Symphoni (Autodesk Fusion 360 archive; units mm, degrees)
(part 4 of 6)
sketch "Sketch2" plane through (0, 0, -5) normal (0, 0, -1) x axis (1, 0, 0)
  circle C1 centre (0, 0) radius 39
  circle C2 centre (0, 0) radius 53.6774
  circle C3 centre (0, 0) radius 55.2268
  circle C4 centre (0, 0) radius 50
  circle C5 centre (0.6259, 42.9954) radius 7
  point P1 (0, 0)
  point P3 (0, 0)
  point P4 (0, 0)
  coincident P1 P3
  coincident P1 P4
  tangent C4 C5
  dimension "d85" diameter C4 = 100
  dimension "d86" diameter C5 = 14
work_plane "WorkPlane3" AlongDistance -70
sketch "Sketch7" plane through (-70, 0, 0) normal (1, 0, 0) x axis (0, 1, 0)
  circle C1 centre (0, 0) radius 2.5
  point P1 (0, 0)
  point P2 (0, 0)
  coincident P1 P2
  dimension "d88" diameter C1 = 5
extrude "Extrude5" cut sketch "Sketch7" along normal blind 140
split "Split2"
move "Move1"
sketch "Sketch8" plane through (0, 0, 18) normal (0, 0, 1) x axis (-1, 0, 0)
  circle C1 centre (0, 0) radius 53.6774
  circle C2 centre (0, 0) radius 48.4417
  circle C3 centre (0, 0) radius 50.9417
  circle C4 centre (0, 0) radius 52.9417
  concentric C1 C3
  concentric C3 C4
  dimension "d91" distance C3 C4 = 2
  dimension "d92" distance C2 C3 = 2.5
extrude "Extrude6" add sketch "Sketch8" profile of C3 C4 along normal blind 3 taper -2
move "Move2"
combine "Combine1"
sketch "involute_gear (9)" plane through (0, 0, -5) normal (0, 0, -1) x axis (1, 0, 0)
  line L1 (54.638, 6.1152) -> (54.716, 6.3779)
  line L2 (54.5535, 5.8691) -> (54.638, 6.1152)
  line L3 (54.4648, 5.642) -> (54.5535, 5.8691)
  line L4 (54.3723, 5.4318) -> (54.4648, 5.642)
  line L5 (54.2784, 5.2404) -> (54.3723, 5.4318)
  line L6 (54.1826, 5.0642) -> (54.2784, 5.2404)
  line L7 (54.0879, 4.9062) -> (54.1826, 5.0642)
  line L8 (53.9943, 4.7639) -> (54.0879, 4.9062)
  line L9 (53.8171, 4.5275) -> (53.9943, 4.7639)
  line L10 (53.66, 4.3508) -> (53.8171, 4.5275)
  line L11 (53.5321, 4.2292) -> (53.66, 4.3508)
  line L12 (53.459, 4.1692) -> (53.5321, 4.2292)
  line L13 (53.3037, 4.1163) -> (53.459, 4.1692)
  line L14 (53.1104, 4.0419) -> (53.3037, 4.1163)
  line L15 (52.9362, 3.9591) -> (53.1104, 4.0419)
  line L16 (52.7815, 3.8694) -> (52.9362, 3.9591)
  line L17 (52.6463, 3.7745) -> (52.7815, 3.8694)
  line L18 (52.531, 3.6756) -> (52.6463, 3.7745)
  line L19 (52.4355, 3.5744) -> (52.531, 3.6756)
  line L20 (52.3599, 3.4723) -> (52.4355, 3.5744)
  line L21 (52.3039, 3.3708) -> (52.3599, 3.4723)
  line L22 (52.2674, 3.2713) -> (52.3039, 3.3708)
  line L23 (52.2502, 3.1753) -> (52.2674, 3.2713)
  line L24 (52.2517, 3.0842) -> (52.2502, 3.1753)
  line L25 (52.2754, 2.9893) -> (52.2517, 3.0842)
  line L26 (52.376, 2.7657) -> (52.2754, 2.9893)
  line L27 (52.5309, 2.377) -> (52.376, 2.7657)
  line L28 (52.6621, 1.9798) -> (52.5309, 2.377)
  line L29 (52.7287, 1.7438) -> (52.6621, 1.9798)
  line L30 (52.7716, 1.6559) -> (52.7287, 1.7438)
  line L31 (52.8289, 1.5851) -> (52.7716, 1.6559)
  line L32 (52.9039, 1.5227) -> (52.8289, 1.5851)
  line L33 (52.9957, 1.4699) -> (52.9039, 1.5227)
  line L34 (53.1039, 1.4281) -> (52.9957, 1.4699)
  line L35 (53.2275, 1.3985) -> (53.1039, 1.4281)
  line L36 (53.3657, 1.3823) -> (53.2275, 1.3985)
  line L37 (53.5176, 1.3808) -> (53.3657, 1.3823)
  line L38 (53.6821, 1.3949) -> (53.5176, 1.3808)
  line L39 (53.8583, 1.4257) -> (53.6821, 1.3949)
  line L40 (54.0449, 1.4742) -> (53.8583, 1.4257)
  line L41 (54.2409, 1.5414) -> (54.0449, 1.4742)
  line L42 (54.3938, 1.6008) -> (54.2409, 1.5414)
  line L43 (54.4884, 1.6018) -> (54.3938, 1.6008)
  line L44 (54.6645, 1.5908) -> (54.4884, 1.6018)
  line L45 (54.8985, 1.5564) -> (54.6645, 1.5908)
  line L46 (55.1861, 1.4893) -> (54.8985, 1.5564)
  line L47 (55.3493, 1.4404) -> (55.1861, 1.4893)
  line L48 (55.5234, 1.3802) -> (55.3493, 1.4404)
  line L49 (55.71, 1.3069) -> (55.5234, 1.3802)
  line L50 (55.905, 1.2206) -> (55.71, 1.3069)
  line L51 (56.111, 1.119) -> (55.905, 1.2206)
  line L52 (56.3249, 1.0021) -> (56.111, 1.119)
  line L53 (56.5479, 0.8678) -> (56.3249, 1.0021)
  line L54 (56.7765, 0.7168) -> (56.5479, 0.8678)
  line L55 (56.9853, 0.566) -> (56.7765, 0.7168)
  line L56 (56.7765, -0.7168) -> (56.9853, -0.566)
  line L57 (56.5479, -0.8678) -> (56.7765, -0.7168)
  line L58 (56.3249, -1.0021) -> (56.5479, -0.8678)
  line L59 (56.111, -1.119) -> (56.3249, -1.0021)
  line L60 (55.905, -1.2206) -> (56.111, -1.119)
  line L61 (55.71, -1.3069) -> (55.905, -1.2206)
  line L62 (55.5234, -1.3802) -> (55.71, -1.3069)
  line L63 (55.3493, -1.4404) -> (55.5234, -1.3802)
  line L64 (55.1861, -1.4893) -> (55.3493, -1.4404)
  line L65 (54.8985, -1.5564) -> (55.1861, -1.4893)
  line L66 (54.6645, -1.5908) -> (54.8985, -1.5564)
  line L67 (54.4884, -1.6018) -> (54.6645, -1.5908)
  line L68 (54.3938, -1.6008) -> (54.4884, -1.6018)
  line L69 (54.2409, -1.5414) -> (54.3938, -1.6008)
  line L70 (54.0449, -1.4742) -> (54.2409, -1.5414)
  line L71 (53.8583, -1.4257) -> (54.0449, -1.4742)
  line L72 (53.6821, -1.3949) -> (53.8583, -1.4257)
  line L73 (53.5176, -1.3808) -> (53.6821, -1.3949)
  line L74 (53.3657, -1.3823) -> (53.5176, -1.3808)
  line L75 (53.2275, -1.3985) -> (53.3657, -1.3823)
  line L76 (53.1039, -1.4281) -> (53.2275, -1.3985)
  line L77 (52.9957, -1.4699) -> (53.1039, -1.4281)
  line L78 (52.9039, -1.5227) -> (52.9957, -1.4699)
  line L79 (52.8289, -1.5851) -> (52.9039, -1.5227)
  line L80 (52.7716, -1.6559) -> (52.8289, -1.5851)
  line L81 (52.7287, -1.7438) -> (52.7716, -1.6559)
  line L82 (52.6621, -1.9798) -> (52.7287, -1.7438)
  line L83 (52.5309, -2.377) -> (52.6621, -1.9798)
  line L84 (52.376, -2.7657) -> (52.5309, -2.377)
  line L85 (52.2754, -2.9893) -> (52.376, -2.7657)
  line L86 (52.2517, -3.0842) -> (52.2754, -2.9893)
  line L87 (52.2502, -3.1753) -> (52.2517, -3.0842)
  line L88 (52.2674, -3.2713) -> (52.2502, -3.1753)
  line L89 (52.3039, -3.3708) -> (52.2674, -3.2713)
  line L90 (52.3599, -3.4723) -> (52.3039, -3.3708)
  line L91 (52.4355, -3.5744) -> (52.3599, -3.4723)
  line L92 (52.531, -3.6756) -> (52.4355, -3.5744)
  line L93 (52.6463, -3.7745) -> (52.531, -3.6756)
  line L94 (52.7815, -3.8694) -> (52.6463, -3.7745)
  line L95 (52.9362, -3.9591) -> (52.7815, -3.8694)
  line L96 (53.1104, -4.0419) -> (52.9362, -3.9591)
  line L97 (53.3037, -4.1163) -> (53.1104, -4.0419)
  line L98 (53.459, -4.1692) -> (53.3037, -4.1163)
  line L99 (53.5321, -4.2292) -> (53.459, -4.1692)
  line L100 (53.66, -4.3508) -> (53.5321, -4.2292)
  line L101 (53.8171, -4.5275) -> (53.66, -4.3508)
  line L102 (53.9943, -4.7639) -> (53.8171, -4.5275)
  line L103 (54.0879, -4.9062) -> (53.9943, -4.7639)
  line L104 (54.1826, -5.0642) -> (54.0879, -4.9062)
  line L105 (54.2784, -5.2404) -> (54.1826, -5.0642)
  line L106 (54.3723, -5.4318) -> (54.2784, -5.2404)
  line L107 (54.4648, -5.642) -> (54.3723, -5.4318)
  line L108 (54.5535, -5.8691) -> (54.4648, -5.642)
  line L109 (54.638, -6.1152) -> (54.5535, -5.8691)
  line L110 (54.716, -6.3779) -> (54.638, -6.1152)
  line L111 (54.7791, -6.6277) -> (54.716, -6.3779)
  line L112 (53.7945, -7.476) -> (54.0514, -7.4948)
  line L113 (53.5223, -7.4448) -> (53.7945, -7.476)
  line L114 (53.2652, -7.4044) -> (53.5223, -7.4448)
  line L115 (53.0262, -7.3564) -> (53.2652, -7.4044)
  line L116 (52.8031, -7.3019) -> (53.0262, -7.3564)
  line L117 (52.5983, -7.2426) -> (52.8031, -7.3019)
  line L118 (52.4082, -7.1789) -> (52.5983, -7.2426)
  line L119 (52.2361, -7.1131) -> (52.4082, -7.1789)
  line L120 (52.0797, -7.0456) -> (52.2361, -7.1131)
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sketch "External_Gear1" plane through (0, 0, -5) normal (0, 0, -1) x axis (0.9995, -0.032, 0)
  line L1 (56.5597, -8.8414) -> (56.452, -9.1587)
  line L2 (56.6721, -8.5508) -> (56.5597, -8.8414)
  line L3 (56.7891, -8.2821) -> (56.6721, -8.5508)
  line L4 (56.9077, -8.0385) -> (56.7891, -8.2821)
  line L5 (57.0253, -7.8204) -> (56.9077, -8.0385)
  line L6 (57.1424, -7.6235) -> (57.0253, -7.8204)
  line L7 (57.2543, -7.4522) -> (57.1424, -7.6235)
  line L8 (57.3622, -7.3011) -> (57.2543, -7.4522)
  line L9 (57.4622, -7.1728) -> (57.3622, -7.3011)
  line L10 (57.6361, -6.9758) -> (57.4622, -7.1728)
  line L11 (57.7628, -6.8542) -> (57.6361, -6.9758)
  line L12 (57.8308, -6.7991) -> (57.7628, -6.8542)
  line L13 (58.0327, -6.6822) -> (57.8308, -6.7991)
  line L14 (58.2072, -6.5612) -> (58.0327, -6.6822)
  line L15 (58.3543, -6.4383) -> (58.2072, -6.5612)
  line L16 (58.4741, -6.3156) -> (58.3543, -6.4383)
  line L17 (58.567, -6.195) -> (58.4741, -6.3156)
  line L18 (58.6334, -6.0786) -> (58.567, -6.195)
  line L19 (58.6739, -5.9684) -> (58.6334, -6.0786)
  line L20 (58.6891, -5.8663) -> (58.6739, -5.9684)
  line L21 (58.6798, -5.7743) -> (58.6891, -5.8663)
  line L22 (58.6524, -5.7035) -> (58.6798, -5.7743)
  line L23 (58.4547, -5.3658) -> (58.6524, -5.7035)
  line L24 (58.3043, -5.0887) -> (58.4547, -5.3658)
  line L25 (58.1617, -4.8075) -> (58.3043, -5.0887)
  line L26 (57.9961, -4.453) -> (58.1617, -4.8075)
  line L27 (57.9534, -4.3902) -> (57.9961, -4.453)
  line L28 (57.883, -4.3303) -> (57.9534, -4.3902)
  line L29 (57.7903, -4.2848) -> (57.883, -4.3303)
  line L30 (57.6766, -4.2555) -> (57.7903, -4.2848)
  line L31 (57.5431, -4.244) -> (57.6766, -4.2555)
  line L32 (57.3911, -4.252) -> (57.5431, -4.244)
  line L33 (57.222, -4.2809) -> (57.3911, -4.252)
  line L34 (57.0373, -4.3321) -> (57.222, -4.2809)
  line L35 (56.8386, -4.407) -> (57.0373, -4.3321)
  line L36 (56.6277, -4.5068) -> (56.8386, -4.407)
  line L37 (56.5437, -4.5315) -> (56.6277, -4.5068)
  line L38 (56.3716, -4.5666) -> (56.5437, -4.5315)
  line L39 (56.1108, -4.5978) -> (56.3716, -4.5666)
  line L40 (55.9484, -4.6072) -> (56.1108, -4.5978)
  line L41 (55.7627, -4.6102) -> (55.9484, -4.6072)
  line L42 (55.5582, -4.605) -> (55.7627, -4.6102)
  line L43 (55.3296, -4.5895) -> (55.5582, -4.605)
  line L44 (55.0833, -4.5624) -> (55.3296, -4.5895)
  line L45 (54.8155, -4.5216) -> (55.0833, -4.5624)
  line L46 (54.5279, -4.4653) -> (54.8155, -4.5216)
  line L47 (54.2248, -4.3927) -> (54.5279, -4.4653)
  line L48 (53.9026, -4.3011) -> (54.2248, -4.3927)
  line L49 (53.6006, -4.2018) -> (53.9026, -4.3011)
  line L50 (53.5185, -2.743) -> (53.2973, -2.9712)
  line L51 (53.7613, -2.5121) -> (53.5185, -2.743)
  line L52 (53.9959, -2.307) -> (53.7613, -2.5121)
  line L53 (54.2244, -2.1235) -> (53.9959, -2.307)
  line L54 (54.4426, -1.9629) -> (54.2244, -2.1235)
  line L55 (54.6481, -1.8244) -> (54.4426, -1.9629)
  line L56 (54.8433, -1.7045) -> (54.6481, -1.8244)
  line L57 (55.0219, -1.6048) -> (54.8433, -1.7045)
  line L58 (55.1877, -1.5212) -> (55.0219, -1.6048)
  line L59 (55.3359, -1.454) -> (55.1877, -1.5212)
  line L60 (55.5814, -1.3604) -> (55.3359, -1.454)
  line L61 (55.7501, -1.3116) -> (55.5814, -1.3604)
  line L62 (55.8359, -1.2944) -> (55.7501, -1.3116)
  line L63 (56.069, -1.2847) -> (55.8359, -1.2944)
  line L64 (56.2797, -1.2587) -> (56.069, -1.2847)
  line L65 (56.4671, -1.2183) -> (56.2797, -1.2587)
  line L66 (56.6303, -1.1653) -> (56.4671, -1.2183)
  line L67 (56.7686, -1.1017) -> (56.6303, -1.1653)
  line L68 (56.8815, -1.0294) -> (56.7686, -1.1017)
  line L69 (56.9685, -0.9507) -> (56.8815, -1.0294)
  line L70 (57.0294, -0.8674) -> (56.9685, -0.9507)
  line L71 (57.064, -0.7816) -> (57.0294, -0.8674)
  line L72 (57.0725, -0.7061) -> (57.064, -0.7816)
  line L73 (57.0545, -0.3152) -> (57.0725, -0.7061)
  line L74 (57.05, 0) -> (57.0545, -0.3152)
  line L75 (57.0545, 0.3152) -> (57.05, 0)
  line L76 (57.0725, 0.7061) -> (57.0545, 0.3152)
  line L77 (57.064, 0.7816) -> (57.0725, 0.7061)
  line L78 (57.0294, 0.8674) -> (57.064, 0.7816)
  line L79 (56.9685, 0.9507) -> (57.0294, 0.8674)
  line L80 (56.8815, 1.0295) -> (56.9685, 0.9507)
  line L81 (56.7686, 1.1017) -> (56.8815, 1.0295)
  line L82 (56.6303, 1.1653) -> (56.7686, 1.1017)
  line L83 (56.4671, 1.2183) -> (56.6303, 1.1653)
  line L84 (56.2797, 1.2588) -> (56.4671, 1.2183)
  line L85 (56.069, 1.2847) -> (56.2797, 1.2588)
  line L86 (55.8359, 1.2944) -> (56.069, 1.2847)
  line L87 (55.7501, 1.3116) -> (55.8359, 1.2944)
  line L88 (55.5814, 1.3604) -> (55.7501, 1.3116)
  line L89 (55.3359, 1.454) -> (55.5814, 1.3604)
  line L90 (55.1877, 1.5211) -> (55.3359, 1.454)
  line L91 (55.0219, 1.6048) -> (55.1877, 1.5211)
  line L92 (54.8433, 1.7045) -> (55.0219, 1.6048)
  line L93 (54.6481, 1.8244) -> (54.8433, 1.7045)
  line L94 (54.4426, 1.9629) -> (54.6481, 1.8244)
  line L95 (54.2244, 2.1235) -> (54.4426, 1.9629)
  line L96 (53.9959, 2.307) -> (54.2244, 2.1235)
  line L97 (53.7613, 2.5121) -> (53.9959, 2.307)
  line L98 (53.5185, 2.743) -> (53.7613, 2.5121)
  line L99 (53.2973, 2.9712) -> (53.5185, 2.743)
  line L100 (53.9026, 4.3011) -> (53.6006, 4.2018)
  line L101 (54.2248, 4.3927) -> (53.9026, 4.3011)
  line L102 (54.5279, 4.4653) -> (54.2248, 4.3927)
  line L103 (54.8155, 4.5216) -> (54.5279, 4.4653)
  line L104 (55.0833, 4.5624) -> (54.8155, 4.5216)
  line L105 (55.3296, 4.5895) -> (55.0833, 4.5624)
  line L106 (55.5582, 4.605) -> (55.3296, 4.5895)
  line L107 (55.7627, 4.6102) -> (55.5582, 4.605)
  line L108 (55.9484, 4.6072) -> (55.7627, 4.6102)
  line L109 (56.1108, 4.5978) -> (55.9484, 4.6072)
  line L110 (56.3716, 4.5666) -> (56.1108, 4.5978)
  line L111 (56.5437, 4.5315) -> (56.3716, 4.5666)
  line L112 (56.6277, 4.5068) -> (56.5437, 4.5315)
  line L113 (56.8386, 4.407) -> (56.6277, 4.5068)
  line L114 (57.0373, 4.3321) -> (56.8386, 4.407)
  line L115 (57.222, 4.2809) -> (57.0373, 4.3321)
  line L116 (57.3911, 4.252) -> (57.222, 4.2809)
  line L117 (57.5431, 4.244) -> (57.3911, 4.252)
  line L118 (57.6766, 4.2555) -> (57.5431, 4.244)
  line L119 (57.7903, 4.2848) -> (57.6766, 4.2555)
  line L120 (57.883, 4.3303) -> (57.7903, 4.2848)
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extrude "Extrude8" add sketch "External_Gear1" along normal blind 10
extrude "Extrude7" new body sketch "External_Gear1" along normal blind 10
position "Position9"
sketch "Sketch13" plane through (0, 0, -19.815) normal (0, 0, 1) x axis (-1, 0, 0)
  line L1 (-96.81, 0.1409) -> (-93.19, 0.1409)
  line L2 (-96.81, 6.3591) -> (-96.81, 0.1409)
  line L3 (-93.19, 6.3591) -> (-96.81, 6.3591)
  line L4 (-93.19, 0.1409) -> (-93.19, 6.3591)
  line L5 (-96.81, 6.3591) -> (-93.19, 0.1409)
  line L6 (-93.19, 6.3591) -> (-96.81, 0.1409)
  circle C1 centre (-95, 3.25) radius 3.5
  circle C2 centre (-95, 3.25) radius 2.5
  circle C3 centre (-95, 3.25) radius 2.5
  point P8 (-95, 3.25)
  point P3 (-95, 3.25)
  point P6 (-96.81, 6.3591)
  point P7 (-93.19, 6.3591)
  concentric C1 C3
  horizontal L1
  perpendicular L1 L2
  parallel L1 L3
  parallel L2 L4
  coincident L5 P8
  coincident L6 P8
  coincident P3 P8
  dimension "d109" distance P6 P7 = 3.62
extrude "Extrude8" new body sketch "Sketch13" profile of C2 C3 L2 L4 along normal blind 8.65
sketch "Sketch14" plane through (0, 0, -15) normal (0, 0, -1) x axis (1, 0, 0)
  line L1 (63.9478, -12.0081) -> (63.7009, -12.2082)
  line L2 (64.1993, -11.7867) -> (63.9478, -12.0081)
  line L3 (64.4245, -11.5713) -> (64.1993, -11.7867)
  line L4 (64.6275, -11.3599) -> (64.4245, -11.5713)
  line L5 (64.8069, -11.1569) -> (64.6275, -11.3599)
  line L6 (64.963, -10.9645) -> (64.8069, -11.1569)
  line L7 (65.0998, -10.7807) -> (64.963, -10.9645)
  line L8 (65.2149, -10.6116) -> (65.0998, -10.7807)
  line L9 (65.313, -10.4539) -> (65.2149, -10.6116)
  line L10 (65.393, -10.3122) -> (65.313, -10.4539)
  line L11 (65.508, -10.0761) -> (65.393, -10.3122)
  line L12 (65.5716, -9.9123) -> (65.508, -10.0761)
  line L13 (65.5964, -9.8284) -> (65.5716, -9.9123)
  line L14 (65.6267, -9.597) -> (65.5964, -9.8284)
  line L15 (65.6713, -9.3895) -> (65.6267, -9.597)
  line L16 (65.7282, -9.2064) -> (65.6713, -9.3895)
  line L17 (65.7955, -9.0486) -> (65.7282, -9.2064)
  line L18 (65.8711, -8.9165) -> (65.7955, -9.0486)
  line L19 (65.9531, -8.8105) -> (65.8711, -8.9165)
  line L20 (66.0393, -8.7307) -> (65.9531, -8.8105)
  line L21 (66.1276, -8.6775) -> (66.0393, -8.7307)
  line L22 (66.2162, -8.6507) -> (66.1276, -8.6775)
  line L23 (66.2921, -8.6489) -> (66.2162, -8.6507)
  line L24 (66.6798, -8.7015) -> (66.2921, -8.6489)
  line L25 (66.9934, -8.734) -> (66.6798, -8.7015)
  line L26 (67.3078, -8.7575) -> (66.9934, -8.734)
  line L27 (67.6987, -8.7742) -> (67.3078, -8.7575)
  line L28 (67.7731, -8.7894) -> (67.6987, -8.7742)
  line L29 (67.8555, -8.8314) -> (67.7731, -8.7894)
  line L30 (67.9331, -8.8995) -> (67.8555, -8.8314)
  line L31 (68.0038, -8.9932) -> (67.9331, -8.8995)
  line L32 (68.0657, -9.1121) -> (68.0038, -8.9932)
  line L33 (68.1168, -9.2555) -> (68.0657, -9.1121)
  line L34 (68.1551, -9.4227) -> (68.1168, -9.2555)
  line L35 (68.1788, -9.6129) -> (68.1551, -9.4227)
  line L36 (68.186, -9.8251) -> (68.1788, -9.6129)
  line L37 (68.1749, -10.0582) -> (68.186, -9.8251)
  line L38 (68.1844, -10.1451) -> (68.1749, -10.0582)
  line L39 (68.2181, -10.3176) -> (68.1844, -10.1451)
  line L40 (68.2896, -10.5703) -> (68.2181, -10.3176)
  line L41 (68.3433, -10.7239) -> (68.2896, -10.5703)
  line L42 (68.4119, -10.8965) -> (68.3433, -10.7239)
  line L43 (68.4953, -11.0833) -> (68.4119, -10.8965)
  line L44 (68.5975, -11.2883) -> (68.4953, -11.0833)
  line L45 (68.7171, -11.5053) -> (68.5975, -11.2883)
  line L46 (68.8577, -11.7369) -> (68.7171, -11.5053)
  line L47 (69.0202, -11.9808) -> (68.8577, -11.7369)
  line L48 (69.2037, -12.2327) -> (69.0202, -11.9808)
  line L49 (69.4121, -12.495) -> (69.2037, -12.2327)
  line L50 (69.6198, -12.7356) -> (69.4121, -12.495)
  line L51 (70.9982, -12.2507) -> (70.8725, -12.5427)
  line L52 (71.118, -11.9379) -> (70.9982, -12.2507)
  line L53 (71.2172, -11.6425) -> (71.118, -11.9379)
  line L54 (71.2988, -11.361) -> (71.2172, -11.6425)
  line L55 (71.3633, -11.0978) -> (71.2988, -11.361)
  line L56 (71.4121, -10.8549) -> (71.3633, -11.0978)
  line L57 (71.4478, -10.6286) -> (71.4121, -10.8549)
  line L58 (71.4712, -10.4254) -> (71.4478, -10.6286)
  line L59 (71.4847, -10.2401) -> (71.4712, -10.4254)
  line L60 (71.4897, -10.0775) -> (71.4847, -10.2401)
  line L61 (71.4818, -9.815) -> (71.4897, -10.0775)
  line L62 (71.4621, -9.6404) -> (71.4818, -9.815)
  line L63 (71.445, -9.5546) -> (71.4621, -9.6404)
  line L64 (71.3643, -9.3357) -> (71.445, -9.5546)
  line L65 (71.3073, -9.1311) -> (71.3643, -9.3357)
  line L66 (71.2727, -8.9426) -> (71.3073, -9.1311)
  line L67 (71.2589, -8.7716) -> (71.2727, -8.9426)
  line L68 (71.2645, -8.6195) -> (71.2589, -8.7716)
  line L69 (71.2877, -8.4875) -> (71.2645, -8.6195)
  line L70 (71.327, -8.3769) -> (71.2877, -8.4875)
  line L71 (71.3805, -8.2886) -> (71.327, -8.3769)
  line L72 (71.4464, -8.2238) -> (71.3805, -8.2886)
  line L73 (71.5128, -8.1869) -> (71.4464, -8.2238)
  line L74 (71.8806, -8.0533) -> (71.5128, -8.1869)
  line L75 (72.1734, -7.9363) -> (71.8806, -8.0533)
  line L76 (72.4627, -7.811) -> (72.1734, -7.9363)
  line L77 (72.8166, -7.6441) -> (72.4627, -7.811)
  line L78 (72.8896, -7.623) -> (72.8166, -7.6441)
  line L79 (72.982, -7.622) -> (72.8896, -7.623)
  line L80 (73.0823, -7.6462) -> (72.982, -7.622)
  line L81 (73.1885, -7.6963) -> (73.0823, -7.6462)
  line L82 (73.2986, -7.7727) -> (73.1885, -7.6963)
  line L83 (73.4105, -7.876) -> (73.2986, -7.7727)
  line L84 (73.5221, -8.0063) -> (73.4105, -7.876)
  line L85 (73.6315, -8.1637) -> (73.5221, -8.0063)
  line L86 (73.7364, -8.3482) -> (73.6315, -8.1637)
  line L87 (73.8349, -8.5597) -> (73.7364, -8.3482)
  line L88 (73.8838, -8.6323) -> (73.8349, -8.5597)
  line L89 (73.9937, -8.7694) -> (73.8838, -8.6323)
  line L90 (74.1745, -8.96) -> (73.9937, -8.7694)
  line L91 (74.2934, -9.071) -> (74.1745, -8.96)
  line L92 (74.4343, -9.1919) -> (74.2934, -9.071)
  line L93 (74.595, -9.3185) -> (74.4343, -9.1919)
  line L94 (74.7808, -9.4527) -> (74.595, -9.3185)
  line L95 (74.9875, -9.5892) -> (74.7808, -9.4527)
  line L96 (75.2196, -9.7289) -> (74.9875, -9.5892)
  line L97 (75.4769, -9.8693) -> (75.2196, -9.7289)
  line L98 (75.7564, -10.0071) -> (75.4769, -9.8693)
  line L99 (76.0629, -10.1425) -> (75.7564, -10.0071)
  line L100 (76.3586, -10.259) -> (76.0629, -10.1425)
  line L101 (77.3537, -9.1891) -> (77.3781, -9.5061)
  line L102 (77.3145, -8.8564) -> (77.3537, -9.1891)
  line L103 (77.265, -8.5487) -> (77.3145, -8.8564)
  line L104 (77.2065, -8.2616) -> (77.265, -8.5487)
  line L105 (77.1412, -7.9986) -> (77.2065, -8.2616)
  line L106 (77.0716, -7.7608) -> (77.1412, -7.9986)
  line L107 (76.998, -7.5439) -> (77.0716, -7.7608)
  line L108 (76.9243, -7.3531) -> (76.998, -7.5439)
  line L109 (76.8502, -7.1828) -> (76.9243, -7.3531)
  line L110 (76.7791, -7.0364) -> (76.8502, -7.1828)
  line L111 (76.65, -6.8076) -> (76.7791, -7.0364)
  line L112 (76.5514, -6.6622) -> (76.65, -6.8076)
  line L113 (76.4964, -6.5942) -> (76.5514, -6.6622)
  line L114 (76.3232, -6.4378) -> (76.4964, -6.5942)
  line L115 (76.1777, -6.2832) -> (76.3232, -6.4378)
  line L116 (76.0594, -6.1324) -> (76.1777, -6.2832)
  line L117 (75.9678, -5.9874) -> (76.0594, -6.1324)
  line L118 (75.902, -5.8501) -> (75.9678, -5.9874)
  line L119 (75.8613, -5.7224) -> (75.902, -5.8501)
  line L120 (75.8446, -5.6062) -> (75.8613, -5.7224)
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  point P679 (67.9652, 2.1729)
  point P684 (67.9652, 2.1729)
  point P682 (66.0452, -0.8271)
  point P683 (69.8852, -0.8271)
  point P681 (66.0452, 5.1729)
  coincident P679 P684
  dimension "d112" diameter = 5.57
  dimension "d113" distance P682 P683 = 3.84
  dimension "d114" distance P681 P682 = 6
  dimension "d145" = 0.2197
extrude "Extrude9" cut sketch "Sketch14" against normal blind 10
component_from_bodies "Body->Comp2"
component_from_bodies "Body->Comp3"
component_from_bodies "Body->Comp4"
as_built_joint "As-built3"
joint "Assemble3" alignAngle 0 alignOffsetX 0 alignOffsetY 0 alignOffsetZ -3
sketch "Sketch15" plane through (0, 0, -36.2) normal (0, 0, -1) x axis (1, 0, 0)
  line L1 (79.2152, 11.1729) -> (79.2152, -23.3271)
  line L2 (58.7152, 13.1729) -> (77.2152, 13.1729)
  line L3 (56.7152, -23.3271) -> (56.7152, 11.1729)
  line L4 (60.9652, -23.3271) -> (56.7152, -23.3271)
  line L5 (60.9652, -34.3271) -> (60.9652, -23.3271)
  line L6 (74.9652, -34.3271) -> (60.9652, -34.3271)
  line L7 (74.9652, -23.3271) -> (74.9652, -34.3271)
  line L8 (79.2152, -23.3271) -> (74.9652, -23.3271)
  line L9 (65.4652, -30.7993) -> (65.4652, -31.7993)
  line L10 (64.9246, -30.7993) -> (65.4652, -30.7993)
  line L11 (64.9246, -27.7993) -> (64.9246, -30.7993)
  line L12 (70.9246, -27.7993) -> (64.9246, -27.7993)
  line L13 (70.9246, -30.7993) -> (70.9246, -27.7993)
  line L14 (70.4652, -30.7993) -> (70.9246, -30.7993)
  line L15 (70.4652, -31.7993) -> (70.4652, -30.7993)
  line L16 (65.4652, -31.7993) -> (70.4652, -31.7993)
  line L17 (88.7324, 34) -> (50, 34)
  line L18 (88.7324, -38.6719) -> (88.7324, 34)
  line L19 (50, -38.6719) -> (88.7324, -38.6719)
  line L20 (50, 34) -> (50, -38.6719)
  arc A1 centre (77.2152, 11.1729) radius 2 clockwise from (77.2152, 13.1729) to (79.2152, 11.1729)
  arc A2 centre (58.7152, 11.1729) radius 2 clockwise from (56.7152, 11.1729) to (58.7152, 13.1729)
  circle C1 centre (77.2152, -21.3271) radius 1.25
  circle C2 centre (59.2152, -18.3271) radius 1.5
  circle C3 centre (58.7152, -21.3271) radius 1.25
  circle C4 centre (67.9652, 2.1729) radius 2.5
  circle C5 centre (76.7152, -18.3271) radius 1.5
  horizontal L17
  vertical L18
  horizontal L19
  vertical L20
extrude "Extrude10" new body sketch "Sketch15" along normal blind 28.8
as_built_joint "As-built4"
motion_link "MotionLink1" Value1 360 Value2 27.692 (= "( 360 / 13 ) * 1 deg")
extrude "Extrude9" add sketch "Sketch5" profile of C2 C3 L1 L2 L3 L4 L9 L10 L11 L12 against normal blind 5
fillet "Fillet1" radius 12.5 7.5
fillet "Fillet2" radius 5 5
sketch "Sketch16" plane through (0, 0, -65) normal (0, 0, -1) x axis (1, 0, 0)
  line L1 (10.1399, 28.3333) -> (9.8601, 28.3333)
  line L2 (10.1399, 58.3333) -> (10.1399, 28.3333)
  line L3 (-9.8601, 58.3333) -> (10.1399, 58.3333)
  line L4 (-9.8601, 31.6667) -> (-9.8601, 58.3333)
  line L5 (-28.3333, 10.1399) -> (-28.3333, 9.8601)
  line L6 (-58.3333, 10.1399) -> (-28.3333, 10.1399)
  line L7 (-58.3333, -9.8601) -> (-58.3333, 10.1399)
  line L8 (-31.6667, -9.8601) -> (-58.3333, -9.8601)
  arc A1 centre (0, 0) radius 30 clockwise from (9.8601, 28.3333) to (28.3333, 9.8601)
  arc A2 centre (30, 0) radius 10 clockwise from (28.3333, 9.8601) to (28.3333, -9.8601)
  arc A3 centre (0, 30) radius 10 clockwise from (-9.8601, 28.3333) to (-9.8601, 31.6667)
  arc A4 centre (-30, 0) radius 10 clockwise from (-28.3333, -9.8601) to (-31.6667, -9.8601)
  circle C1 centre (0, 0) radius 22.8035
  arc A5 centre (0, 0) radius 30 clockwise from (-28.3333, 9.8601) to (-9.8601, 28.3333)
  arc A6 centre (0, 0) radius 30 clockwise from (28.3333, -9.8601) to (-28.3333, -9.8601)
  concentric A1 C1
extrude "Extrude10" cut sketch "Sketch16" profile of C1 against normal blind 45
sketch "Sketch17" plane through (88.7324, 0, 0) normal (1, 0, 0) x axis (0, 1, 0)
  line L1 (-34, -36.2) -> (38.6719, -36.2)
  line L2 (-34, -65) -> (-34, -36.2)
  line L3 (38.6719, -65) -> (-34, -65)
  line L4 (38.6719, -36.2) -> (38.6719, -65)
  line L5 (30, -65) -> (-20, -65)
  line L6 (30, -45) -> (30, -65)
  line L7 (-20, -45) -> (30, -45)
  line L8 (-20, -65) -> (-20, -45)
  point P6 (-20, -65)
  horizontal L5
  vertical L6
  horizontal L7
  vertical L8
  coincident L3 P6
extrude "Extrude11" cut sketch "Sketch17" profile of L3 L5 L6 L7 L8 against normal blind 40
sketch "Sketch18" plane through (0, 0, -36.2) normal (0, 0, 1) x axis (-1, 0, 0)
  line L1 (-70.4652, -30.7993) -> (-70.4652, -31.7993)
  line L2 (-70.9246, -30.7993) -> (-70.4652, -30.7993)
  line L3 (-70.9246, -27.7993) -> (-70.9246, -30.7993)
  line L4 (-64.9246, -27.7993) -> (-70.9246, -27.7993)
  line L5 (-64.9246, -30.7993) -> (-64.9246, -27.7993)
  line L6 (-65.4652, -30.7993) -> (-64.9246, -30.7993)
  line L7 (-65.4652, -31.7993) -> (-65.4652, -30.7993)
  line L8 (-70.4652, -31.7993) -> (-65.4652, -31.7993)
  line L9 (-50, -38.6719) -> (-88.7324, -38.6719)
  line L10 (-50, 34) -> (-50, -38.6719)
  line L11 (-88.7324, 34) -> (-50, 34)
  line L12 (-88.7324, -38.6719) -> (-88.7324, 34)
  line L13 (-50, 34) -> (-88.7324, 34)
  line L14 (-50, 23.8238) -> (-50, 34)
  line L15 (-88.7324, 23.8238) -> (-50, 23.8238)
  line L16 (-88.7324, 34) -> (-88.7324, 23.8238)
  circle C1 centre (-59.2152, -18.3271) radius 1.5
  circle C2 centre (-67.9652, 2.1729) radius 2.5
  circle C3 centre (-76.7152, -18.3271) radius 1.5
  circle C4 centre (-58.7152, -21.3271) radius 1.25
  circle C5 centre (-77.2152, -21.3271) radius 1.25
  circle C6 centre (-67.9652, 15.6729) radius 1.25
  circle C7 centre (-67.9652, 15.6729) radius 1.25
  point P21 (-50, 23.8238)
  point P18 (-88.7324, 34)
  point P19 (-88.7324, 34)
  horizontal L13
  vertical L14
  horizontal L15
  vertical L16
  coincident L10 P21
  coincident P18 P19
extrude "Extrude12" cut sketch "Sketch18" profile of L10 L11 L12 L13 L14 L15 L16 against normal blind 25
extrude "Extrude13" cut sketch "Sketch18" profile of C6 C7 against normal blind 30
sketch "Sketch19" plane through (0, 38.6719, 0) normal (0, 1, 0) x axis (-1, 0, 0)
  line L1 (-88.7324, -36.2) -> (-50, -36.2)
  line L2 (-88.7324, -65) -> (-88.7324, -36.2)
  line L3 (-50, -65) -> (-88.7324, -65)
  line L4 (-50, -36.2) -> (-50, -65)
  line L5 (-50, -60.2819) -> (-88.7324, -60.2819)
  line L6 (-50, -65) -> (-50, -60.2819)
  line L7 (-88.7324, -65) -> (-50, -65)
  line L8 (-88.7324, -60.2819) -> (-88.7324, -65)
  point P5 (-50, -65)
  point P8 (-50, -65)
  point P6 (-88.7324, -60.2819)
  horizontal L5
  vertical L6
  horizontal L7
  vertical L8
  coincident P5 P8
  coincident L2 P6
extrude "Extrude14" add sketch "Sketch19" profile of L2 L3 L4 L5 L6 L7 L8 along normal blind 10
sketch "Sketch20" plane through (0, 0, -61.2) normal (0, 0, 1) x axis (-1, 0, 0)
  line L1 (-50, 23.8238) -> (-88.7324, 23.8238)
  line L2 (-50, 34) -> (-50, 23.8238)
  line L3 (-88.7324, 34) -> (-50, 34)
  line L4 (-88.7324, 23.8238) -> (-88.7324, 34)
  line L5 (-88.7324, -38.6719) -> (-50, -38.6719)
  line L6 (-88.7324, -48.6719) -> (-88.7324, -38.6719)
  line L7 (-50, -48.6719) -> (-88.7324, -48.6719)
  line L8 (-50, -38.6719) -> (-50, -48.6719)
  circle C1 centre (-69.3662, 29.4765) radius 1.6
  circle C2 centre (-69.3662, -43.6719) radius 1.6
  dimension "d156" diameter C1 = 3.2
  dimension "d157" diameter C2 = 3.2
hole "Hole1" HoleDepth 10 HoleDiameter 3.2 TipAngle 118
hole "Hole3" HoleDepth 10 HoleDiameter 3.2 TipAngle 118
hole "Hole4" HoleDepth 10 HoleDiameter 3.2 TipAngle 118
circular_pattern "C-Pattern1" TotalAngle 360
hole "Hole5" HoleDepth 10 HoleDiameter 3.2 TipAngle 118
fillet "Fillet3" radius 5 5
offset_faces "OffsetFaces1" distance -7
hole "Hole6" HoleDepth 10 HoleDiameter 3.2 TipAngle 118
fillet "Fillet1" radius 2.5
fillet "Fillet4" radius 3.5
work_plane "WorkPlane4" AlongDistance -5
work_plane "WorkPlane5" AlongDistance -7
split "Split4" bodies "Lower Half (1)", "Lower Half (2)"
sketch "Sketch21" plane through (0, 0, -0.1) normal (0, 0, 1) x axis (-1, 0, 0)
  circle C1 centre (0, 0) radius 30
  circle C2 centre (-24, 0) radius 2.5
  circle C3 centre (24, 0) radius 2.5
  circle C4 centre (0, 0) radius 17
  circle C5 centre (0, 0) radius 25
  circle C6 centre (0, 0) radius 47.2211
  circle C7 centre (0, 0) radius 61.1446
  circle C8 centre (0, 0) radius 30.25
  point P1 (0, 0)
  point P5 (0, 0)
  coincident P1 P5
  concentric C1 C6
  concentric C6 C7
  concentric C5 C8
  dimension "d189" diameter C8 = 60.5
extrude "Extrude1" cut sketch "Sketch21" profile of C6 C7 against normal blind 10
extrude "Extrude11" cut sketch "Sketch21" profile of C2 C3 C4 C5 against normal blind 25
extrude "Extrude13" add sketch "Sketch21" profile of C1 C2 C3 C5 against normal blind 5 bodies "Lower Half (2)"
extrude "Extrude14" add sketch "Sketch21" profile of C1 C8 along normal blind 5
combine "Combine2" bodies "Lower Half (1)"
offset_faces "OffsetFaces1" distance 7
sketch "Sketch22" plane through (0, 0, 4.9) normal (0, 0, 1) x axis (-1, 0, 0)
  circle C1 centre (-24, 0) radius 2.5
  circle C2 centre (24, 0) radius 2.5
  circle C3 centre (0, 0) radius 12.4353
  circle C4 centre (0, 0) radius 19.8494
  circle C5 centre (0, 0) radius 30.25
  concentric C3 C4
extrude "Extrude15" cut sketch "Sketch22" profile of C3 C4 against normal blind 62
sketch "Sketch23" plane through (0, 0, -60) normal (0, 0, 1) x axis (-1, 0, 0)
  circle C1 centre (0, 0) radius 22.8035
  circle C2 centre (0, 0) radius 25
  concentric C1 C2
  dimension "d202" diameter C2 = 50
extrude "Extrude16" cut sketch "Sketch23" along normal blind 60
sketch "Sketch24" plane through (0, 0, -65) normal (0, 0, -1) x axis (1, 0, 0)
  line L1 (-28.3333, 10.1399) -> (-28.3333, 9.8601)
  line L2 (-58.3333, 10.1399) -> (-28.3333, 10.1399)
  line L3 (-58.3333, -9.8601) -> (-58.3333, 10.1399)
  line L4 (-31.6667, -9.8601) -> (-58.3333, -9.8601)
  line L5 (-10.1399, -28.3333) -> (-9.8601, -28.3333)
  line L6 (-10.1399, -58.3333) -> (-10.1399, -28.3333)
  line L7 (9.8601, -58.3333) -> (-10.1399, -58.3333)
  line L8 (9.8601, -31.6667) -> (9.8601, -58.3333)
  line L9 (28.3333, -10.1399) -> (28.3333, -9.8601)
  line L10 (58.3333, -10.1399) -> (28.3333, -10.1399)
  line L11 (58.3333, 9.8601) -> (58.3333, -10.1399)
  line L12 (31.6667, 9.8601) -> (58.3333, 9.8601)
  line L13 (10.1399, 28.3333) -> (9.8601, 28.3333)
  line L14 (10.1399, 58.3333) -> (10.1399, 28.3333)
  line L15 (-9.8601, 58.3333) -> (10.1399, 58.3333)
  line L16 (-9.8601, 31.6667) -> (-9.8601, 58.3333)
  circle C1 centre (43.9204, -0.1471) radius 1.6
  circle C2 centre (-0.148, -42.8843) radius 1.6
  arc A1 centre (-30, 0) radius 10 clockwise from (-28.3333, -9.8601) to (-31.6667, -9.8601)
  arc A2 centre (0, 0) radius 30 clockwise from (-9.8601, -28.3333) to (-28.3333, -9.8601)
  arc A3 centre (0, -30) radius 10 clockwise from (9.8601, -28.3333) to (9.8601, -31.6667)
  arc A4 centre (0, 0) radius 30 clockwise from (28.3333, -9.8601) to (9.8601, -28.3333)
  arc A5 centre (30, 0) radius 10 clockwise from (28.3333, 9.8601) to (31.6667, 9.8601)
  arc A6 centre (0, 0) radius 30 clockwise from (9.8601, 28.3333) to (28.3333, 9.8601)
  arc A7 centre (0, 30) radius 10 clockwise from (-9.8601, 28.3333) to (-9.8601, 31.6667)
  arc A8 centre (0, 0) radius 30 clockwise from (-28.3333, 9.8601) to (-9.8601, 28.3333)
  circle C3 centre (0.6697, 43.6896) radius 1.6
  arc A9 centre (-41.4186, 0.1498) radius 1.6 clockwise from (-39.9843, -0.5594) to (-39.9662, 0.8211)
  arc A10 centre (-30, 0) radius 10 clockwise from (-39.9843, -0.5594) to (-39.9662, 0.8211)
  circle C4 centre (0, 0) radius 30
  circle C5 centre (0, 0) radius 63.6553
  point P1 (0, 0)
  point P37 (0, 0)
  coincident P1 P37
  concentric A2 C5
extrude "Extrude17" cut sketch "Sketch24" against normal blind 15
offset_faces "OffsetFaces1" distance 4.9
offset_faces "OffsetFaces2" distance 10
sketch "Sketch25" plane through (0, 0, 0) normal (0, 1, 0) x axis (1, 0, 0)
  line L1 (-11.2525, 44.7413) -> (11.5885, 44.7413)
  line L2 (-11.2525, 65) -> (-11.2525, 44.7413)
  line L3 (11.5885, 65) -> (-11.2525, 65)
  line L4 (11.5885, 44.7413) -> (11.5885, 65)
  horizontal L1
  vertical L2
  horizontal L3
  vertical L4
extrude "Extrude18" cut sketch "Sketch25" blind 40 from offset 22
chamfer "Chamfer1" distance 8
sketch "Sketch26" plane through (0, 0, 0) normal (0, 1, 0) x axis (1, 0, 0)
  line L1 (-32.9, 5) -> (32.9, 5)
  line L2 (-32.9, 15) -> (32.9, 15)
  line L3 (-19.8494, 0) -> (19.8494, 0)
  line L4 (-19.8494, -4.9) -> (19.8494, -4.9)
  line L5 (19.8494, 0) -> (25, 15)
  line L6 (25.5, 0) -> (19.8494, 0)
  line L7 (25.5, 15) -> (25.5, 0)
  line L8 (25.5, 15) -> (25, 15)
  line L9 (30, 23) -> (32.9, 15)
  line L10 (30, 15) -> (30, 23)
  point P10 (25, 15)
  point P6 (19.8494, 0)
  point P11 (19.8494, 0)
  point P12 (19.8494, 0)
  point P14 (25.5, 15)
  point P4 (32.9, 15)
  point P15 (32.9, 15)
  point P17 (30, 15)
  coincident L2 P10
  coincident P6 P11
  coincident P6 P12
  parallel L3 L6
  coincident L2 P14
  perpendicular L2 L7
  coincident P4 P15
  coincident L2 P17
  perpendicular L2 L10
revolve "Revolve1" sketch "Sketch26" AlongAngle 360
sketch "Sketch27" plane through (0, 0, -60) normal (0, 0, 1) x axis (-1, 0, 0)
  line L1 (-11.5885, -22) -> (-11.5885, -22.1519)
  line L2 (11.2525, -22) -> (-11.5885, -22)
  line L3 (11.2525, -22.3245) -> (11.2525, -22)
  arc A1 centre (0, 0) radius 25 clockwise from (-11.5885, -22.1519) to (11.2525, -22.3245)
  circle C1 centre (0, 13.5716) radius 2.65
  arc A2 centre (0, 0) radius 12.4353 clockwise from (-11, -5.7996) to (11, -5.7996)
  arc A3 centre (0, 0) radius 12.4353 clockwise from (11, -5.7996) to (-11, -5.7996)
  dimension "d212" diameter C1 = 5.3
hole "Hole7" HoleDepth 10 HoleDiameter 5.4 TipAngle 118 CSDiameter 5.94 CSAngle 90
circular_pattern "C-Pattern2" TotalAngle 360
delete_face "DeleteFace1"
sketch "Sketch28" plane through (0, 0, -60.2819) normal (0, 0, 1) x axis (-1, 0, 0)
  line L1 (-50, -41.1719) -> (-50, -48.6719)
  line L2 (-88.7324, -41.1719) -> (-50, -41.1719)
  line L3 (-88.7324, -48.6719) -> (-88.7324, -41.1719)
  line L4 (-50, -48.6719) -> (-88.7324, -48.6719)
  circle C1 centre (-69.3662, -43.6719) radius 1.6
  circle C2 centre (-69.3662, -43.6719) radius 5
  concentric C1 C2
  tangent L4 C2
extrude "Extrude15" cut sketch "Sketch28" profile of L1 L2 L3 L4 C2 against normal blind 10
fillet "Fillet2" radius 17.5
delete_face "DeleteFace2"
sketch "Sketch29" plane through (0, 0, -36.2) normal (0, 0, 1) x axis (-1, 0, 0)
  line L1 (-88.7324, 21.3238) -> (-50, 21.3238)
  line L2 (-88.7324, -36.1719) -> (-88.7324, 21.3238)
  line L3 (-50, -36.1719) -> (-88.7324, -36.1719)
  line L4 (-50, 21.3238) -> (-50, -36.1719)
  line L5 (-70.4652, -30.7993) -> (-70.4652, -31.7993)
  line L6 (-70.9246, -30.7993) -> (-70.4652, -30.7993)
  line L7 (-70.9246, -27.7993) -> (-70.9246, -30.7993)
  line L8 (-64.9246, -27.7993) -> (-70.9246, -27.7993)
  line L9 (-64.9246, -30.7993) -> (-64.9246, -27.7993)
  line L10 (-65.4652, -30.7993) -> (-64.9246, -30.7993)
  line L11 (-65.4652, -31.7993) -> (-65.4652, -30.7993)
  line L12 (-70.4652, -31.7993) -> (-65.4652, -31.7993)
  line L13 (-74.9652, -34.3271) -> (-74.9652, -23.3271)
  line L14 (-60.9652, -34.3271) -> (-74.9652, -34.3271)
  line L15 (-60.9652, -23.3271) -> (-60.9652, -34.3271)
  line L16 (-56.7152, -23.3271) -> (-60.9652, -23.3271)
  line L17 (-56.7152, 11.1729) -> (-56.7152, -23.3271)
  line L18 (-77.2152, 13.1729) -> (-58.7152, 13.1729)
  line L19 (-79.2152, -23.3271) -> (-79.2152, 11.1729)
  line L20 (-74.9652, -23.3271) -> (-79.2152, -23.3271)
  line L21 (-70.9246, -30.7993) -> (-70.4652, -30.7993)
  line L22 (-70.9246, -27.7993) -> (-70.9246, -30.7993)
  line L23 (-64.9246, -27.7993) -> (-70.9246, -27.7993)
  line L24 (-64.9246, -30.7993) -> (-64.9246, -27.7993)
  line L25 (-65.4652, -30.7993) -> (-64.9246, -30.7993)
  line L26 (-65.4652, -31.7993) -> (-65.4652, -30.7993)
  line L27 (-70.4652, -31.7993) -> (-65.4652, -31.7993)
  line L28 (-70.4652, -30.7993) -> (-70.4652, -31.7993)
  line L29 (-56.2152, 11.1729) -> (-56.2152, -23.8271)
  line L30 (-77.2152, 13.6729) -> (-58.7152, 13.6729)
  line L31 (-79.7152, -23.8271) -> (-79.7152, 11.1729)
  line L32 (-75.4652, -23.8271) -> (-79.7152, -23.8271)
  line L33 (-75.4652, -34.8271) -> (-75.4652, -23.8271)
  line L34 (-60.4652, -34.8271) -> (-75.4652, -34.8271)
  line L35 (-60.4652, -23.8271) -> (-60.4652, -34.8271)
  line L36 (-56.2152, -23.8271) -> (-60.4652, -23.8271)
  line L37 (-54.7152, -25.3271) -> (-58.9652, -25.3271)
  line L38 (-54.7152, 11.1729) -> (-54.7152, -25.3271)
  line L39 (-77.2152, 15.1729) -> (-58.7152, 15.1729)
  line L40 (-81.2152, -25.3271) -> (-81.2152, 11.1729)
  line L41 (-76.9652, -25.3271) -> (-81.2152, -25.3271)
  line L42 (-76.9652, -36.3271) -> (-76.9652, -25.3271)
  line L43 (-58.9652, -36.3271) -> (-76.9652, -36.3271)
  line L44 (-58.9652, -25.3271) -> (-58.9652, -36.3271)
  circle C1 centre (-67.9652, 15.6729) radius 1.25
  circle C2 centre (-59.2152, -18.3271) radius 1.5
  circle C3 centre (-58.7152, -21.3271) radius 1.25
  circle C4 centre (-67.9652, 2.1729) radius 2.5
  circle C5 centre (-77.2152, -21.3271) radius 1.25
  circle C6 centre (-76.7152, -18.3271) radius 1.5
  arc A1 centre (-58.7152, 11.1729) radius 2 clockwise from (-58.7152, 13.1729) to (-56.7152, 11.1729)
  arc A2 centre (-77.2152, 11.1729) radius 2 clockwise from (-79.2152, 11.1729) to (-77.2152, 13.1729)
  circle C7 centre (-67.9652, 2.1729) radius 3.5
  circle C8 centre (-67.9652, -8.8271) radius 2
  circle C9 centre (-58.2152, -3.8271) radius 0.75
  circle C10 centre (-58.7152, 11.1729) radius 1
  circle C11 centre (-77.2152, 11.1729) radius 1
  circle C12 centre (-77.7152, -3.8271) radius 0.75
  arc A3 centre (-77.2152, -21.3271) radius 1.25 clockwise from (-76.009, -21.6551) to (-76.2052, -20.5907)
  arc A4 centre (-73.9593, -20.7271) radius 2.25 clockwise from (-76.2052, -20.5907) to (-75.8978, -19.5848)
  arc A5 centre (-76.7152, -18.3271) radius 1.5 clockwise from (-75.8978, -19.5848) to (-75.3572, -18.964)
  arc A6 centre (-73.9593, -20.7271) radius 2.25 clockwise from (-75.3572, -18.964) to (-76.009, -21.6551)
  arc A7 centre (-58.7152, -21.3271) radius 1.25 clockwise from (-59.7253, -20.5907) to (-59.9214, -21.6551)
  arc A8 centre (-61.9712, -20.7271) radius 2.25 clockwise from (-59.9214, -21.6551) to (-60.5733, -18.964)
  arc A9 centre (-59.2152, -18.3271) radius 1.5 clockwise from (-60.5733, -18.964) to (-60.0327, -19.5848)
  arc A10 centre (-61.9712, -20.7271) radius 2.25 clockwise from (-60.0327, -19.5848) to (-59.7253, -20.5907)
  arc A11 centre (-58.7152, 11.1729) radius 2.5 clockwise from (-58.7152, 13.6729) to (-56.2152, 11.1729)
  arc A12 centre (-77.2152, 11.1729) radius 2.5 clockwise from (-79.7152, 11.1729) to (-77.2152, 13.6729)
  arc A13 centre (-58.7152, 11.1729) radius 4 clockwise from (-58.7152, 15.1729) to (-54.7152, 11.1729)
  arc A14 centre (-77.2152, 11.1729) radius 4 clockwise from (-81.2152, 11.1729) to (-77.2152, 15.1729)
  dimension "d224" = 0.5
  dimension "d225" = 2
extrude "Extrude16" new body sketch "Sketch29" profile of C1 L3 L32 L36 L30 L34 L31 L29 A11 L35 A12 L33 L37 L41 A13 L40 L38 L42 L44 L39 A14 along normal blind 5
move "Move1" RotateAngle -90
position "Position10"
sketch "Sketch30" plane through (0, 18.5942, 0) normal (0, 1, 0) x axis (-1, 0, 0)
  line L1 (-27.1205, -38.7) -> (-27.1205, -60.2819)
  line L2 (-87.1162, -36.2) -> (-29.6205, -36.2)
  line L3 (-89.6162, -58.7) -> (-89.6162, -38.7)
  line L4 (-97.2924, -61.2) -> (-92.1162, -61.2)
  line L5 (-99.7924, -65) -> (-99.7924, -63.7)
  line L6 (-88.2924, -65) -> (-99.7924, -65)
  line L7 (-85.7924, -47.5) -> (-85.7924, -62.5)
  line L8 (-38.2924, -45) -> (-83.2924, -45)
  line L9 (-35.7924, -62.5) -> (-35.7924, -47.5)
  line L10 (-24.6205, -65) -> (-33.2924, -65)
  line L11 (-24.6205, -60.2819) -> (-24.6205, -65)
  line L12 (-27.1205, -60.2819) -> (-24.6205, -60.2819)
  line L13 (-32, -65.1301) -> (-85.7924, -65.1301)
  line L14 (-32, -41) -> (-32, -65.1301)
  line L15 (-85.7924, -41) -> (-32, -41)
  line L16 (-85.7924, -65.1301) -> (-85.7924, -41)
  arc A1 centre (-29.6205, -38.7) radius 2.5 clockwise from (-29.6205, -36.2) to (-27.1205, -38.7)
  arc A2 centre (-87.1162, -38.7) radius 2.5 clockwise from (-89.6162, -38.7) to (-87.1162, -36.2)
  arc A3 centre (-92.1162, -58.7) radius 2.5 clockwise from (-89.6162, -58.7) to (-92.1162, -61.2)
  arc A4 centre (-97.2924, -63.7) radius 2.5 clockwise from (-99.7924, -63.7) to (-97.2924, -61.2)
  arc A5 centre (-88.2924, -62.5) radius 2.5 clockwise from (-85.7924, -62.5) to (-88.2924, -65)
  arc A6 centre (-83.2924, -47.5) radius 2.5 clockwise from (-85.7924, -47.5) to (-83.2924, -45)
  arc A7 centre (-38.2924, -47.5) radius 2.5 clockwise from (-38.2924, -45) to (-35.7924, -47.5)
  arc A8 centre (-33.2924, -62.5) radius 2.5 clockwise from (-33.2924, -65) to (-35.7924, -62.5)
  horizontal L13
  vertical L14
  horizontal L15
  vertical L16
extrude "Extrude17" cut sketch "Sketch30" profile of A6 L8 A7 L9 A8 L10 L14 L15 L16 against normal blind 50
move "Move1"
work_plane "WorkPlane7"
sketch "Sketch32" plane through (0, -2.1729, 0) normal (0, -1, 0) x axis (-1, 0, 0)
  line L1 (-30, 36.6938) -> (-85.3041, 36.6938)
  line L2 (-30, 64.9956) -> (-30, 36.6938)
  line L3 (-40, 64.9956) -> (-30, 64.9956)
  line L4 (-40, 41.2) -> (-40, 64.9956)
  line L5 (-80, 41.2) -> (-40, 41.2)
  line L6 (-80, 64.9956) -> (-80, 41.2)
  line L7 (-96.2951, 64.9956) -> (-80, 64.9956)
  line L8 (-96.2951, 59.9956) -> (-96.2951, 64.9956)
  line L9 (-85, 59.9956) -> (-96.2951, 59.9956)
  line L10 (-85, 36.6938) -> (-85, 59.9956)
  line L11 (-76.9652, 36.2) -> (-42.4652, 36.2)
  line L12 (-20, 64.9956) -> (-30, 64.9956)
  line L13 (-30, 36.6938) -> (-20, 64.9956)
  point P12 (-85, 36.6938)
  horizontal L1
  perpendicular L1 L2
  perpendicular L2 L3
  perpendicular L3 L4
  perpendicular L4 L5
  perpendicular L5 L6
  perpendicular L6 L7
  perpendicular L7 L8
  perpendicular L8 L9
  coincident L1 P12
  perpendicular L1 L10
  perpendicular L2 L12
  dimension "d232" distance L6 L10 = 5
  dimension "d233" distance L2 L4 = 10
  dimension "d235" distance L7 L9 = 5
extrude "Extrude1" new body sketch "Sketch32" profile of L1 L2 L3 L4 L5 L6 L7 L8 L9 L10 L12 L13 distance 20
split "Split1"
sketch "Sketch33" plane through (0, -22.1729, 0) normal (0, -1, 0) x axis (1, 0, 0)
  line L1 (20.208, -64.9956) -> (20.208, -64.4069)
  line L2 (40, -64.9956) -> (20.208, -64.9956)
  line L3 (40, -41.2) -> (40, -64.9956)
  line L4 (80, -41.2) -> (40, -41.2)
  line L5 (80, -64.9956) -> (80, -41.2)
  line L6 (96.2951, -64.9956) -> (80, -64.9956)
  line L7 (96.2951, -59.9956) -> (96.2951, -64.9956)
  line L8 (85, -59.9956) -> (96.2951, -59.9956)
  line L9 (85, -36.6938) -> (85, -59.9956)
  line L10 (30, -36.6938) -> (85, -36.6938)
  line L11 (20.208, -64.4069) -> (30, -36.6938)
  line L12 (40, -54.9956) -> (3.4237, -54.9956)
  line L13 (40, -64.9956) -> (40, -54.9956)
  line L14 (3.4237, -64.9956) -> (40, -64.9956)
  line L15 (3.4237, -54.9956) -> (3.4237, -64.9956)
  point P4 (40, -64.9956)
  point P15 (40, -64.9956)
  point P14 (40, -54.9956)
  horizontal L12
  vertical L13
  horizontal L14
  vertical L15
  coincident P4 P15
  dimension "d238" distance P14 P15 = 10
extrude "Extrude18" new body sketch "Sketch33" profile of L1 L2 L3 L11 L12 L13 L14 L15 along normal blind 7.6
split "Split2"
remove_body "RemoveBody1"
remove_body "RemoveBody5"
sketch "Sketch34" plane through (0, 17.8271, 0) normal (0, 1, 0) x axis (-1, 0, 0)
  line L1 (-24.1287, -53.3107) -> (-24.1287, -64.9956)
  line L2 (-30, -36.6938) -> (-24.1287, -53.3107)
  line L3 (-85, -36.6938) -> (-30, -36.6938)
  line L4 (-85, -59.9956) -> (-85, -36.6938)
  line L5 (-96.2951, -59.9956) -> (-85, -59.9956)
  line L6 (-96.2951, -64.9956) -> (-96.2951, -59.9956)
  line L7 (-80, -64.9956) -> (-96.2951, -64.9956)
  line L8 (-80, -41.2) -> (-80, -64.9956)
  line L9 (-40, -41.2) -> (-80, -41.2)
  line L10 (-40, -64.9956) -> (-40, -41.2)
  line L11 (-24.1287, -64.9956) -> (-40, -64.9956)
  line L12 (-11.6355, -55) -> (-40, -55)
  line L13 (-11.6355, -65) -> (-11.6355, -55)
  line L14 (-40, -65) -> (-11.6355, -65)
  line L15 (-40, -55) -> (-40, -65)
  point P13 (-40, -55)
  horizontal L12
  vertical L13
  horizontal L14
  vertical L15
  coincident L10 P13
extrude "Extrude19" new body sketch "Sketch34" profile of L1 L10 L11 L12 L13 L14 L15 along normal blind 9.8
sketch "Sketch35" plane through (0, 27.6271, 0) normal (0, 1, 0) x axis (-1, 0, 0)
  line L1 (-11.6355, -65) -> (-40, -65)
  line L2 (-11.6355, -55) -> (-11.6355, -65)
  line L3 (-40, -55) -> (-11.6355, -55)
  line L4 (-40, -65) -> (-40, -55)
  circle C1 centre (-32, -60) radius 1.6
  dimension "d243" diameter C1 = 3.2
extrude "Extrude20" cut sketch "Sketch35" profile of C1 against normal blind 69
